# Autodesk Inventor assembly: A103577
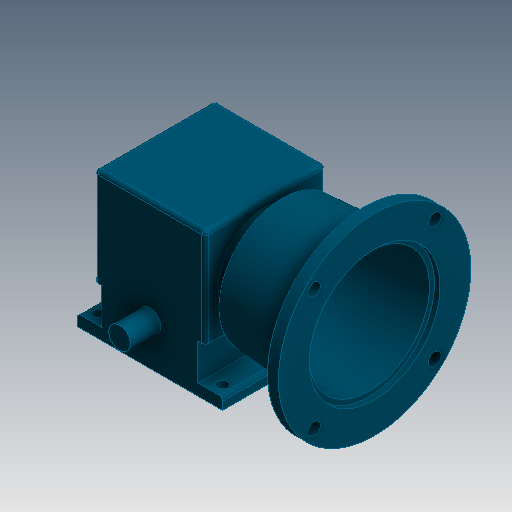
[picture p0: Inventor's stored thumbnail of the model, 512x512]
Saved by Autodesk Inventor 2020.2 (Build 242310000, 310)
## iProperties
Created: 1999-12
Part Number: A103577
Document SubType Name: Assembly
Designer: glanglot
Mass: 11357.9 g
Surface Area: 1844.19 cm^2
Volume: 1724.91 cm^3
Density: 6.58463 g/cm^3
Control State: 0
Checked Out: False
Last Check In By: glanglot
Last Check In Date: 1999-12-14
Master: False
Shininess: 0.0
Length Units: 11272
Angle Units: 11279
Time Units: 11290
Mass Units: 11286
Length Display Precision: 3
Angle Display Precision: 2
Compacted: True
Dimensions: 6,6x6,6x8,2 in
Mass: 25,04 lb
DocNumber: A103577.iam
Folder: 01 - Themengebiete\Simplification\01 - Packaging machine\
VDS_Category: 3D Komponenten
Density: 0.0
Volumn: 0.0
Area: 0.0
PropertySet Name: Model Information
Author: glanglot
Revision Number: -
Title: gearbox with flanch
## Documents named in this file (3)
- D:\07 - DEMODATEN\OTX 2019 - Dataset - UPDATE - Dez2019\Designs\07-Packing machine\A103577.iam
- D:\07 - DEMODATEN\OTX 2019 - Dataset - UPDATE - Dez2019\Designs\07-Packing machine\Parts\ADSK-011761.ipt
- D:\07 - DEMODATEN\OTX 2019 - Dataset - UPDATE - Dez2019\Designs\07-Packing machine\Parts\ADSK-011762.ipt
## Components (2 placed, 2 different names)
1. ADSK-011761:1 — Flush:1, Passend:1
2. ADSK-011762:1 — Flush:1, Passend:1
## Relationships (2: Flush 1, Mate 1)
- Flush:1: ADSK-011761:1 ↔ ADSK-011762:1
- Passend:1 [Mate]: ADSK-011761:1 ↔ ADSK-011762:1
